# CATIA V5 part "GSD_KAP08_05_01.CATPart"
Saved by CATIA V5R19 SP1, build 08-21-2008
Part number: GSD_ANALYSIS_04
Description: Beispielmodell für Krümmungsanalyse mit Stacheln.  Maik Hertha IT Consultants
Bounding box of the stored display mesh (mm): x -27.272 to 98.166, y -101.144 to -66.759, z 36.437 to 46.521
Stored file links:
  \GSD_BUCH_UEBUNG\GSD_KAP08_05_01.CATPart
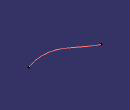
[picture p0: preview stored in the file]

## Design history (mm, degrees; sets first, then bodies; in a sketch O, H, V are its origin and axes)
AxisSystem1: origin (0, 0, 0), X (1, 0, 0), Y (0, 1, 0), Z (0, 0, 1)
Set1
  DatumSurface1
  DatumCurve1
  Plane1: type Equation, A 0, B 0, C 1, RefAxis AxisSystem1, Length 20
Body1 (main body)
